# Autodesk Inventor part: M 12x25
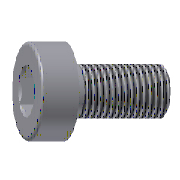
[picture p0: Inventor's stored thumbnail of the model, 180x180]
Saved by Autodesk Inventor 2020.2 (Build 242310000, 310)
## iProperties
Manager: www.cadconsulting.pl
Company: Fabian Stasiak CAD Consulting
IsCustomPart: 0
Created: 2014-02
Part Number: M 12x25
Material: Stal, miękka
Description: Socket Head Cap Screw DIN 912 - 12.9
Document SubType Name: Modeling
Designer: F.Stasiak
Standard Revision: 1
Manufacturer: DME
Language: pl-PL
Size Designation: 12x25
Categories: <MemberInstance><Categories><Category DisplayName="Forma wtryskowa" InternalName="349578f2-f4d4-4954-8c09-8e99297a61c0" Mnemonic="MOLD"><Category DisplayName="C
Mass: 0.133121 g
Surface Area: 2.01441 cm^2
Volume: 0.133121 cm^3
Density: 7.85 g/cm^3
Appearance: Częściowo polerowana
Catalog Web Link: www.expertbooks.pl
Author: F.Stasiak
Subject: Zbiór ćwiczeń. Autodesk Inventor 2020. Kurs Professional
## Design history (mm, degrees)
sketch "Sketch1"
  geometry: L1 (0, -32.4)-(0, 19.4) reference; L2 (5.774, 12)-(9, 12); L3 (9, 12)-(9, 0); L4 (9, 0)-(6, 0); L5 (6, 0)-(6, -25); L6 (6, -25)-(0, -25); L7 (0, 2.996)-(0, -25); L8 (0, 2.996)-(5, 6); L9 (5, 6)-(5, 11.226); L10 (5, 11.226)-(5.774, 12); 1 further point
  constraints: 18 end point, 4 vertical, 3 horizontal, 2 point on line
  dimensions: "d0" = 18 diameter of L3 L1 (= dk); "d1" = 12 distance between parallel lines of L4 L2 (= k); "d2" = 12 diameter of L5 L1 (= d); "d3" = 25 distance between parallel lines of L6 L4 (= L); "d4" = 59 deg angle of L1 L8; "d5" = 45 deg angle of L1 L10; "d6" = 10 diameter of L9 L1 (= sw); "d7" = 11.54701 diameter of L2.start L1 (= 1.1547 x sw); "d8" = 6 distance from line of L8.end L2 (= t)
revolve "Revolution1" sketch "Sketch1" stored, may be unused: angle "d44" = 90 deg
sketch "Sketch2"
  geometry: L1 (0, 5.774)-(5, 2.887); L2 (5, 2.887)-(5, -2.887); L3 (5, -2.887)-(0, -5.774); L4 (0, -5.774)-(-5, -2.887); L5 (-5, -2.887)-(-5, 2.887); L6 (-5, 2.887)-(0, 5.774); 3 further points
  constraints: 12 end point, 2 vertical alignment, 1 coincident, 14 other
extrude "Extrusion1" cut sketch "Sketch2" taper "d9" = 0 deg; stored distance "d45" = 10
thread "Thread1" dims "d10" = 25 (= b), "d11" = 0
chamfer "Chamfer1" distance "d12" = 0.875 (= 0.5 x P); stored, may be unused: second distance "d50" = 2, angle "d51" = 45 deg
fillet "Fillet1" dims "d13" = 0.875 (= 0.5 x P)
body "Solid1"
other parameters: "d" = 12 [user parameter; used in 1 equation term], "L" = 25 [user parameter; used in 1 equation term], "dk" = 18 [user parameter; used in 1 equation term], "b" = 25 [user parameter; used in 1 equation term], "k" = 12 [user parameter; used in 1 equation term], "sw" = 10 [user parameter; used in 2 equation terms], "t" = 6 [user parameter; used in 1 equation term], "P" = 1.75 [user parameter; used in 2 equation terms], "d14" = 0, "d15" = 0, "d55" = 0
